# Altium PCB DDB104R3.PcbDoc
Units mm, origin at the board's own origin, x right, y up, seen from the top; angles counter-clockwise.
Board outline 65 x 55 mm, 2 copper layers (Top Layer, Bottom Layer); 24 components, 8 nets, 66 pads, 9 vias.
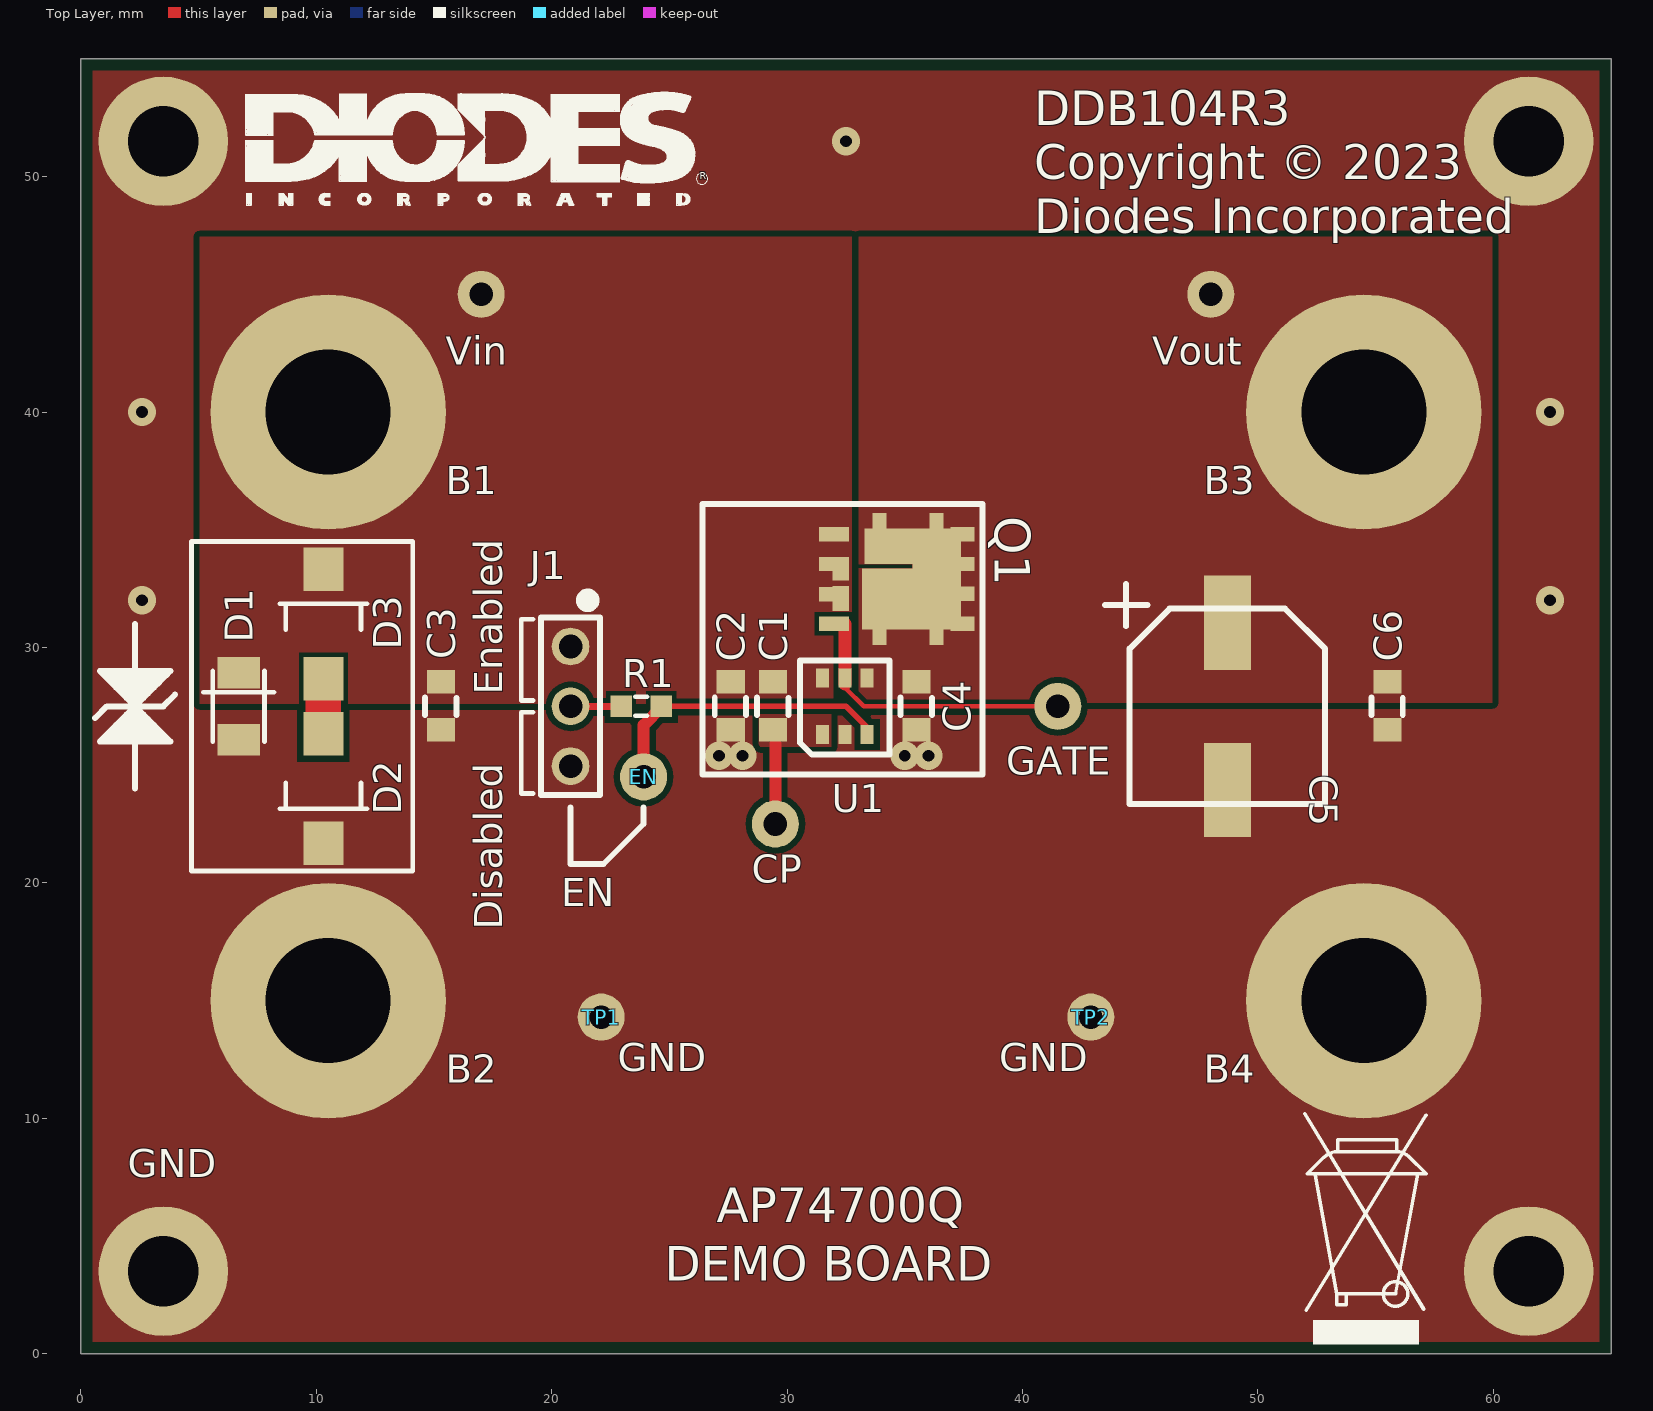
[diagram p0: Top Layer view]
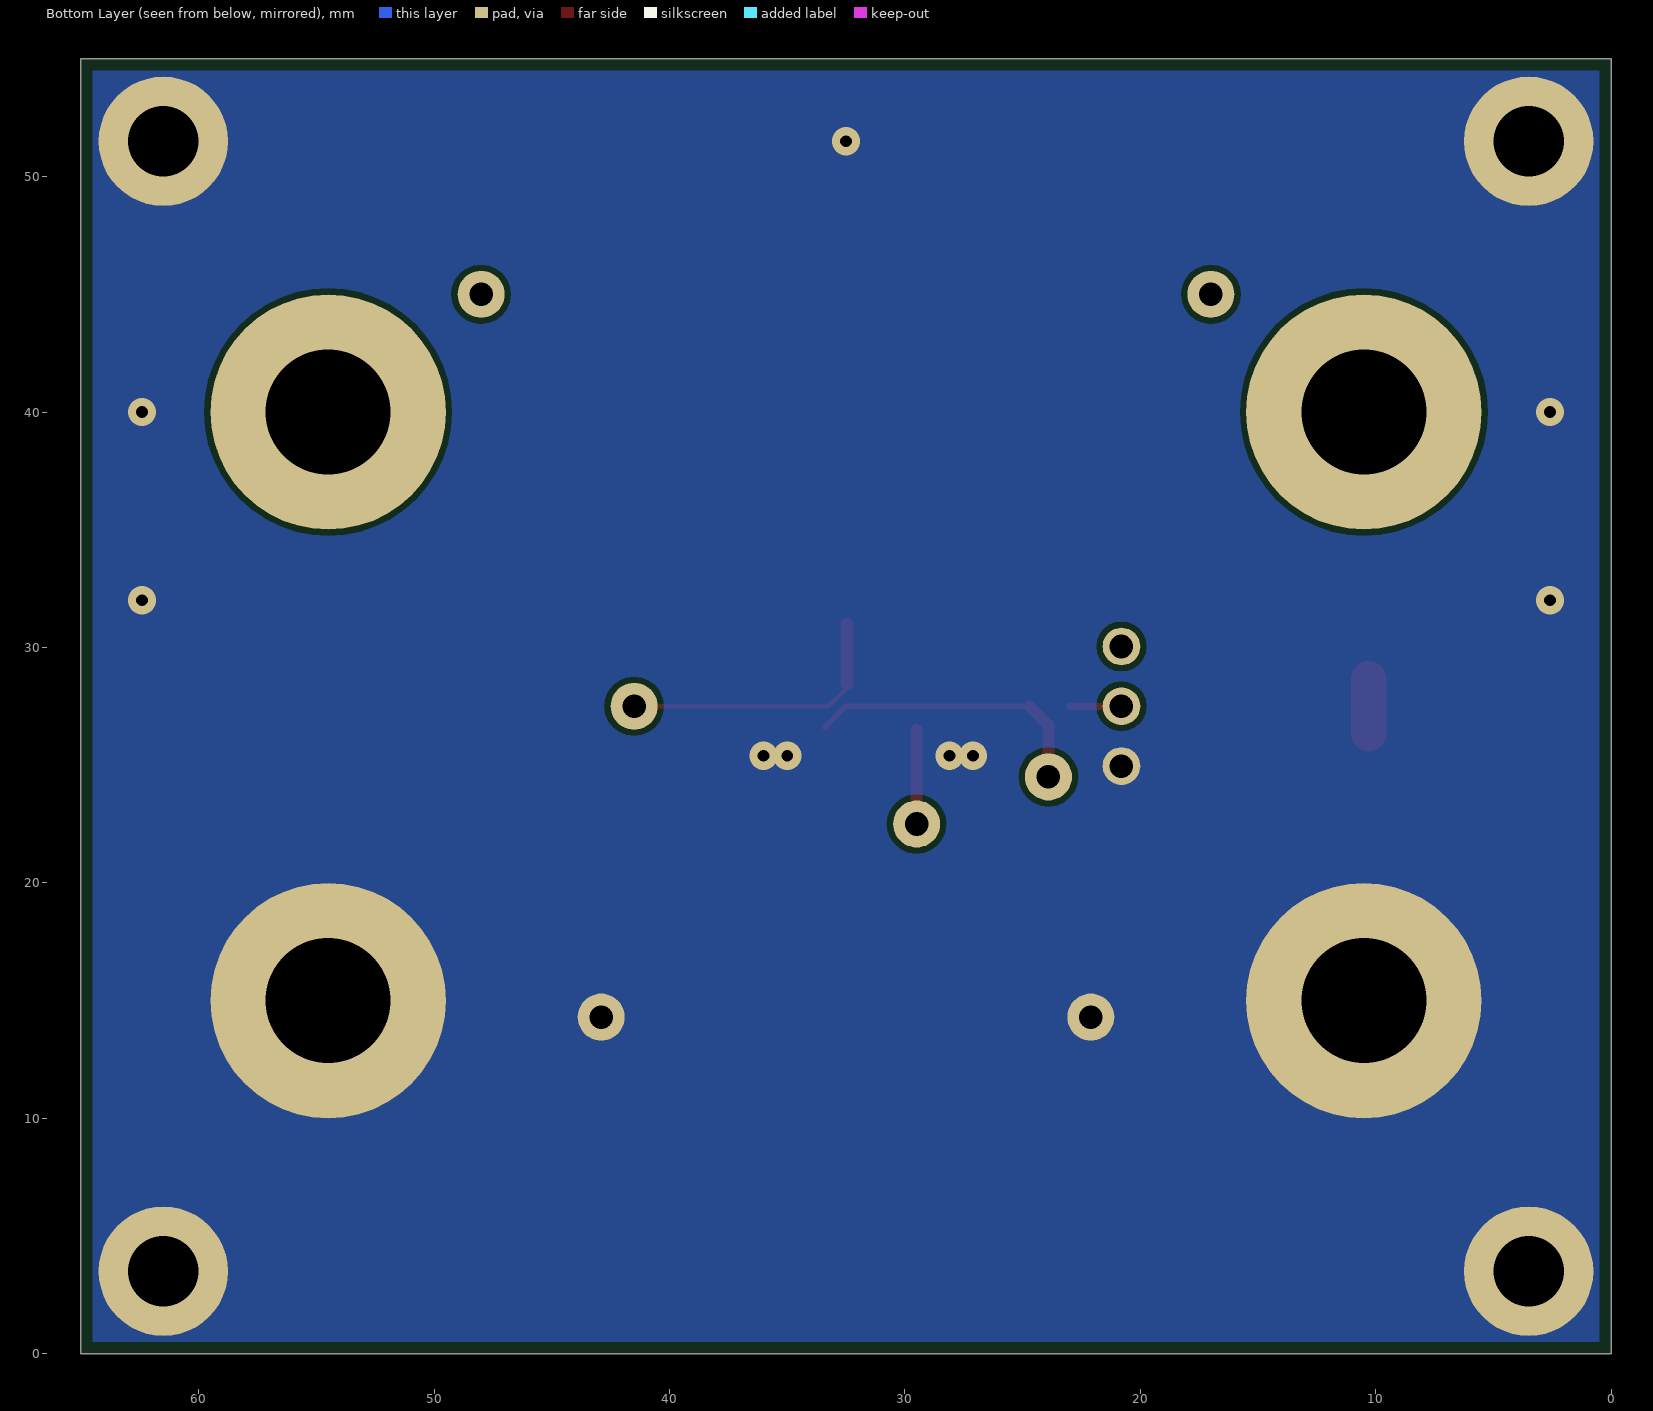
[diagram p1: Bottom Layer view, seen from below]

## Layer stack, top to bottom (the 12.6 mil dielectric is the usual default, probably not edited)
Top Layer: signal copper 0.0356
Dielectric: dielectric 0.32, FR-4, Dk 4.8
Bottom Layer: signal copper 0.0356

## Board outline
0,0 65,0 65,55 0,55

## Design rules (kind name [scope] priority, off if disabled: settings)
Clearance Clearance_2 [(InNet('GND'))] p1: gap=0.25
Clearance Clearance_1 [(IsPad AND OnLayer('Multi-Layer'))] p2: gap=0.25
Clearance [All] p3: gap=0.2
ComponentClearance [All] p1: gap=0.254 collisioncheckmode=3 verticalgap=0.254
HoleSize [All] p1: absolutevalues=TRUE maxlimit=10 minlimit=0.2 maxpercent=80.000 minpercent=20.000
PlaneClearance [All] p1: clearance=0.1
PolygonConnect [All] p1: connectstyle=Direct reliefconductorwidth=0.254 reliefentries=4 polygonreliefangle="90 Angle"
RoutingVias [All] p1: holewidth=0.711 width=1.27 viastyle="Through Hole" minholewidth=0.5 minwidth=0.5 maxholewidth=1.5 maxwidth=1.5
SolderMaskExpansion [All] p1: expansion=0.102
TestPointUsage [All] p1: valid=0 allowmultiple=FALSE
Testpoint [All] p1: side=15 testpointundercomponent=TRUE minsize=1.016 maxsize=2.54 preferedsize=1.524 minholesize=0 maxholesize=1.016 preferedholesize=0.813 testpointgrid=0.025 style=1023 order=0-112345678
Width [All] p1: maxlimit=2 minlimit=0.2 preferedwidth=0.254
16 further rules are at their usual default settings.

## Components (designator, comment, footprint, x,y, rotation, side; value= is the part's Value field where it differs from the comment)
B1 "Banana Socket 4mm" "Banana Plug" 10.5,40 r0 top
B2 "Banana Socket 4mm" "Banana Plug" 10.5,15 r0 top
B3 "Banana Socket 4mm" "Banana Plug" 54.5,40 r0 top
B4 "Banana Socket 4mm" "Banana Plug" 54.5,15 r0 top
C1 "Capacitor" 0805 29.4,27.5 r90 top
C2 "Capacitor" 0805 27.6,27.5 r90 top
C3 "Capacitor" 0805 15.3,27.5 r90 top
C4 "Capacitor" 0805 35.5,27.5 r90 top
C5 "Capacitor" "Case F Cap" 48.7,27.5 r0 top
C6 "Capacitor" 0805 55.5,27.5 r90 top
CP "Test Point" TestPoint#1 29.5,22.5 r0 top
D1 "SMF4L30CAQ" SMF4Lxx(C)AQ 6.7,27.5 r90 top
D2 "P6SMAJ26ADFQ" P6SMAJxxADFQ 10.3,24 r90 top
D3 "P6SMAJ43ADFQ" P6SMAJxxADFQ 10.3,31 r270 top
EN "Test Point" TestPoint#1 23.9,24.5 r0 top
GATE "Test Point" TestPoint#2 38,27.5 r90 top
J1 "3W header" "0.1\" 3W" 20.8,27.5 r270 top
Q1 "PowerDI3333+PowerDI5060" PowerDI3333+5060 33.775,32.075 r270 top
R1 "Resistance" 0603 23.8,27.5 r0 top
TP1 "Test Point" TestPoint#1 22.1,14.3 r90 top
TP2 "Test Point" TestPoint#1 42.9,14.3 r90 top
U1 "AP74700" SOT26 32.5,27.5 r0 top
Vin "Test Point" TestPoint#1 17,45 r90 top
Vout "Test Point" TestPoint#1 48,45 r90 top

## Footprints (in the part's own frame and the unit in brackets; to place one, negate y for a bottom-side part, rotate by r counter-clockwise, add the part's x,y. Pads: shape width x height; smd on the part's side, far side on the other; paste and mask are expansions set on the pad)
"0.1\" 3W" [mm]
  round 1.6 hole 1: 1(-2.54,0) 2(0,0) 3(2.54,0)
  silkscreen extent -4.75,-1.25 3.77,1.25, body extent -3.77,-1.25 3.77,1.25, height 8
0603 [mm]
  rect 0.9x0.9 smd: 1(-0.85,0) 2(0.85,0)
  silkscreen extent -0.25,-0.4 0.25,0.4, body extent -1.4,-0.55 1.4,0.55
0805 [mm]
  rect 1x1.2 smd: 1(-1,0) 2(1.05,0)
  silkscreen extent -0.38,-0.65 0.38,0.67, body extent -1.65,-0.7 1.65,0.7
"Banana Plug" [mm]
  round 10 hole 5.3: 1(0,0)
"Case F Cap" [mm]
  rect 2x4 smd: 1(0,3.55) 2(0,-3.55)
  silkscreen extent -5.2,-4.15 4.15,5.2, body extent -4.15,-4.15 4.15,4.15
P6SMAJxxADFQ [mm]
  rect 1.85x1.7 smd: 0(-2.325,0) 1(2.325,0)
  silkscreen extent -0.85,-1.85 0.25,1.85, body extent -2.3,-1.47 2.3,1.47
PowerDI3333+5060 [mm]
  rect 0.61x1.27 smd: 1(-2.74,-1.785) 1(-1.47,-1.785) 1(-0.18,-1.785) 2(1.07,-1.785)
  rect 0.42x0.7 smd: 1(-0.975,-1.5) 1(-0.325,-1.5) 1(0.325,-1.5) 2(0.975,-1.5) 3(-0.975,1.5) 3(-0.325,1.5) 3(0.326,1.5) 3(0.975,1.5)
  rect 0.61x1.02 smd: 3(-2.74,3.68) 3(-1.47,3.68) 3(-0.2,3.68) 3(1.07,3.68)
  rect 1.98x0.6 smd: 3(-2.65,0.15)
  rect 1.52x4.03 smd: 3(-2.225,1.525)
  rect 5.61x0.6 smd: 3(-0.835,2.575)
  rect 4.3x2.067 smd: 3(-0.835,2.575)
  rect 2.6x2.2 smd: 3(0.015,0.5)
  rect 1.989x0.6 smd: 3(0.975,0.15)
  body extent -3.35,-2.1 1.65,3.9
SMF4Lxx(C)AQ [mm]
  rect 1.34x1.8 smd: 0(1.43,0) 1(-1.43,0)
  silkscreen extent -1.5,-1.5 1.5,1.5, body extent -1.45,-1 1.45,1
SOT26 [mm]
  rect 0.55x0.8 smd: 1(-1.002,-1.198) 2(-0.052,-1.198) 3(0.898,-1.198) 4(0.898,1.202) 5(-0.052,1.202) 6(-1.002,1.202)
  silkscreen extent -1.95,-2.05 1.85,1.95, body extent -1.55,-1.4 1.45,1.4
TestPoint#1 [mm]
  round 2 hole 1: 1(0,0)
TestPoint#2 [mm]
  round 2 hole 1: 1(0,-3.5)

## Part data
D1: library part SMF4Lxx(C)AQ, "TVS Device"
D2 D3: library part P6SMAJxxADFQ, "TVS Device"
Q1: library part "N-Channel MOSFET"

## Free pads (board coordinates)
  round 5.5 hole 3: 0(3.5,3.5) 0(3.5,51.5) 0(61.5,3.5) 0(61.5,51.5)

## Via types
v1: diameter 1.2, hole 0.5, Top Layer to Bottom Layer, tented both sides, 9 vias

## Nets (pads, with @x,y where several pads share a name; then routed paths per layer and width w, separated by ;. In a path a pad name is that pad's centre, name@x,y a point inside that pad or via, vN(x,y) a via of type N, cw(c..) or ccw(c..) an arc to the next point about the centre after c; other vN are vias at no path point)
GND: B2.1 B4.1 C2.1 C3.1 C4.1 C5.2 C6.1 D1.1 D2.0 J1.3 pad.0 TP1.1 TP2.1 U1.2
  other v1: 27.1,25.4 28.1,25.4 35,25.4 36,25.4 2.6,32 62.4,32 2.6,40 62.4,40 32.5,51.5
NetC1_1: C1.1 CP.1 U1.1 | length 4
  Top Layer w0.5: CP.1 C1.1@29.5,26.5
NetD2_1: D2.1 D3.1 | length 2.4
  Top Layer w1.5: D2.1 D3.1
NetEN_1: EN.1 R1.2 U1.3 | length 12.4
  Top Layer w0.25: R1.2@24.7,27.5 32.5,27.5 U1.3@33.399,26.601
  Top Layer w0.5: EN.1 23.9,26.7 R1.2@24.7,27.5
NetGATE_1: GATE.1 Q1.2 U1.5 | length 11.6
  Top Layer w0.2: U1.5@32.5,28.4 32.5,28.25 33.25,27.5 GATE.1@41.102,27.5
  Top Layer w0.55: U1.5@32.448,28.452 Q1.2@32.448,31
NetJ1_2: J1.2 R1.1 | length 2.2
  Top Layer w0.3: J1.2 R1.1@23,27.5
VIN: B1.1 C1.2 C2.2 C3.2 D1.0 D3.0 J1.1 Q1.1 U1.6 Vin.1
VOUT: B3.1 C4.2 C5.1 C6.2 Q1.3 U1.4 Vout.1

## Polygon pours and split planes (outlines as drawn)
NetC1_1 on Top Layer "Top Layer-No Net" (solid, pour order 1001): 31.875,27.2 28.8,27.2 28.8,25.775 31.875,25.775
VIN on Top Layer "Top Layer-No Net" (solid, pour order 1003): 31.95,27.6 5.05,27.6 5.05,47.45 32.75,47.45 32.75,31.5 31.95,31.5
VOUT on Top Layer "Top Layer-No Net" (solid, pour order 1002): 33.05,27.65 33.05,33.36 35.32,33.36 35.32,33.54 33.05,33.54 33.05,47.45 59.95,47.45 59.95,27.65
GND on Top Layer "Top Layer-No Net" (solid, pour order 1004): 0.5,54.5 0.5,0.5 64.5,0.5 64.5,54.5
GND on Bottom Layer "Top Layer-No Net" (solid, pour order 1005): 0.5,54.5 64.5,54.5 64.5,0.5 0.5,0.5
no net on Top Solder "Top Layer-No Net" (solid, pour order 1006): 0,0 0,6.9 23.2,6.9 23.2,0
no net on Top Solder "Top Layer-No Net" (solid, pour order 1007): 0,0 0,6.9 23.2,6.9 23.2,0
no net on Bottom Solder "Top Layer-No Net" (solid, pour order 1000): 0,0 23.2,0 23.2,6.9 0,6.9

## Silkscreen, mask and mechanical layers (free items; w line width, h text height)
Top Overlay:
  drawing of 484 lines, arcs and shapes, not listed
  text "DDB104R3" at 40.5,51.7 h2.5
  text "R" at 26.29,49.785 h0.5
  text "Copyright © 2023" at 40.5,49.4 h2.5
  text "Diodes Incorporated" at 40.5,47.1 h2.5
  text "Enabled" at 17.9,28 h1.2 r90
  text "EN" at 20.4,19 h1.2
  text "Disabled" at 17.9,18 h1.2 r90
  text "GND" at 22.8,12 h1.2
  text "GND" at 39,12 h1.2
  text "GND" at 2,7.5 h1.2
  text "AP74700Q" at 27,5.1 h2.5
  text "DEMO BOARD" at 24.8,2.6 h2.5
Mechanical 1:
  text "A)      THE CONTROLLING UNIT IS MILLIMETRES" at 71.5,128 h1.8
  text "B)      THE BOARD MUST BE ROHS COMPLIANT" at 71.5,124 h1.8
  text "C)      MATERIAL : LAMINATED SHEET COPPERCLAD TYPE FR-4 OR EQUIVALENT" at 71.5,120 h1.8
  text "2 LAYERS TO BE 1 OZ NOMINAL WITH 1.6MM TOTAL BOARD THICKNESS." at 86.5,116 h1.8
  text "D)      REMOVE ALL BURRS AND SHARP EDGES" at 71.5,112 h1.8
  text "E)      FINISH COAT ALL EXPOSED EXTERNAL COPPER WITH TIN" at 71.5,108 h1.8
  text "F)      SILKSCREEN USING WHITE NON-CONDUCTIVE INK" at 71.5,104 h1.8
  text "REGISTRATION WITH PWB MUST BE +/- 0.125MM" at 86.5,100 h1.8
  text "G)      SOLDERMASK: APPLY BOTH SIDES" at 71.5,96 h1.8
  text "Layer List:" at 71.5,88 h1.8
  text "Top Silk" at 71.5,84 h1.8
  text "Top Solder" at 71.5,80 h1.8
  text "Top Copper" at 71.5,76 h1.8
  text "Top Paste" at 71.5,72 h1.8
  text "Bottom Copper" at 71.5,68 h1.8
  text "Bottom Solder" at 71.5,64 h1.8
  text "Mech 4 (Edge)" at 71.5,60 h1.8
  text "Mech 1 (Instructions)" at 71.5,56 h1.8
Mechanical 4:
  the board outline again, w0.2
